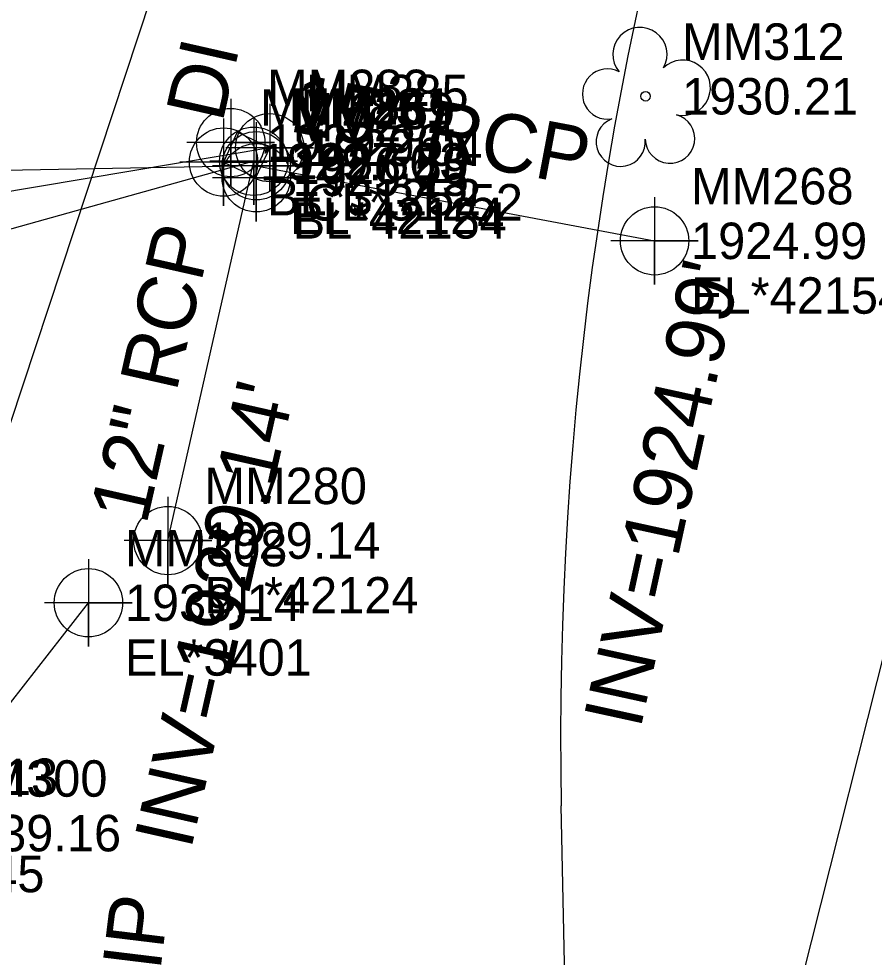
# Model space of a CAD drawing. Extents: x 1004514 to 1005247, y 553695 to 554706.
# Drawn here: x 1004934 to 1004992.7, y 554126.5 to 554190.9 of the extents above; entities that cross this region are included whole.
import ezdxf

# ---------------------------------------------------------------- set-up
doc = ezdxf.new("R2010")
doc.units = 0
for name, color, linetype in [('Exist Building', 7, 'Continuous'), ('Exist Building Cogo Elevation', 7, 'Continuous'), ('Exist Building Cogo Number', 7, 'Continuous'), ('Exist Building Cogo Point CELL', 7, 'Continuous'), ('Exist Property Iron Pin Text', 7, 'Continuous'), ('Exist Right of Way Line', 7, 'Continuous'), ('Exist Structure Minor Drop Inlet', 7, 'Continuous'), ('Exist Structure Minor Drop Inlet Cogo Comment', 7, 'Continuous'), ('Exist Structure Minor Drop Inlet Cogo Elevation', 7, 'Continuous'), ('Exist Structure Minor Drop Inlet Cogo Number', 7, 'Continuous'), ('Exist Structure Minor Drop Inlet Cogo Point CELL', 7, 'Continuous'), ('Exist Structure Minor Drop Inlet Leader', 7, 'Continuous'), ('Exist Structure Minor Drop Inlet Text', 7, 'Continuous'), ('Exist Structure Minor Pipes RCP 12 Inch', 7, 'Continuous'), ('Exist Structure Minor Pipes RCP 12 Inch Cogo Comment', 7, 'Continuous'), ('Exist Structure Minor Pipes RCP 12 Inch Cogo Number', 7, 'Continuous'), ('Exist Structure Minor Pipes RCP 12 Inch Cogo Point CELL', 7, 'Continuous'), ('Exist Structure Minor Pipes RCP 12 Inch Invert', 7, 'Continuous'), ('Exist Structure Minor Pipes RCP 12 Inch Leader', 7, 'Continuous'), ('Exist Structure Minor Pipes RCP 12 Inch Text', 7, 'Continuous'), ('Exist Structure Minor Pipes RCP 15 Inch', 7, 'Continuous'), ('Exist Structure Minor Pipes RCP 15 Inch Cogo Comment', 7, 'Continuous'), ('Exist Structure Minor Pipes RCP 15 Inch Cogo Elevation', 7, 'Continuous'), ('Exist Structure Minor Pipes RCP 15 Inch Cogo Number', 7, 'Continuous'), ('Exist Structure Minor Pipes RCP 15 Inch Cogo Point CELL', 7, 'Continuous'), ('Exist Structure Minor Pipes RCP 15 Inch Invert', 7, 'Continuous'), ('Exist Structure Minor Pipes RCP 15 Inch Leader', 7, 'Continuous'), ('Exist Structure Minor Pipes RCP 15 Inch Text', 7, 'Continuous'), ('Exist Vegetation Tree CELL', 7, 'Continuous'), ('Exist Vegetation Tree Cogo Elevation', 7, 'Continuous'), ('Exist Vegetation Tree Cogo Number', 7, 'Continuous'), ('Exist Vegetation Woods Line Cogo Comment', 7, 'Continuous'), ('Old_Level_3', 7, 'Continuous'), ('Scratch_Level_3', 7, 'Continuous')]:
    doc.layers.add(name, color=color, linetype=linetype)

msp = doc.modelspace()

# ---------------------------------------------------------------- linework, layer by layer
at = {"layer": 'Exist Building'}
msp.add_line((1004926.468, 554135.051), (1004938.808, 554150.855), dxfattribs=at)
at = {"layer": 'Exist Building Cogo Point CELL'}
msp.add_lwpolyline([(1004938.808, 554153.855), (1004938.808, 554147.855), (1004938.808, 554150.855), (1004941.808, 554150.855), (1004935.808, 554150.855)], dxfattribs=at)
msp.add_circle((1004938.808, 554150.855), 2.344, dxfattribs=at)
at = {"layer": 'Exist Right of Way Line'}
msp.add_line((1004974.633, 553969.453), (1004971.246, 554136.929), dxfattribs=at)
msp.add_arc((1005209.198, 554141.741), 238, 143.26447, 181.15854, dxfattribs=at)
at = {"layer": 'Exist Structure Minor Drop Inlet'}
msp.add_lwpolyline([(1004948.079, 554181.091), (1004950.3, 554180.028), (1004951.243, 554182.08), (1004949.022, 554183.143)], close=True, dxfattribs=at)
at = {"layer": 'Exist Structure Minor Drop Inlet Cogo Point CELL'}
for points in [[(1004948.569, 554185.432), (1004948.569, 554179.432), (1004948.569, 554182.432), (1004951.569, 554182.432), (1004945.569, 554182.432)], [(1004951.243, 554185.08), (1004951.243, 554179.08), (1004951.243, 554182.08), (1004954.243, 554182.08), (1004948.243, 554182.08)], [(1004948.079, 554184.091), (1004948.079, 554178.091), (1004948.079, 554181.091), (1004951.079, 554181.091), (1004945.079, 554181.091)], [(1004950.322, 554183.017), (1004950.322, 554177.017), (1004950.322, 554180.017), (1004953.322, 554180.017), (1004947.322, 554180.017)]]:
    msp.add_lwpolyline(points, dxfattribs=at)
for centre in [(1004948.569, 554182.432), (1004951.243, 554182.08), (1004948.079, 554181.091), (1004950.322, 554180.017)]:
    msp.add_circle(centre, 2.344, dxfattribs=at)
at = {"layer": 'Exist Structure Minor Drop Inlet Leader'}
msp.add_lwpolyline([(1004951.243, 554182.08), (1004919.348, 554176.707), (1004921.33, 554184.761)], dxfattribs=at)
at = {"layer": 'Exist Structure Minor Pipes RCP 12 Inch'}
msp.add_line((1004944.265, 554155.124), (1004950.148, 554181.151), dxfattribs=at)
at = {"layer": 'Exist Structure Minor Pipes RCP 12 Inch Cogo Point CELL'}
for points in [[(1004950.148, 554184.151), (1004950.148, 554178.151), (1004950.148, 554181.151), (1004953.148, 554181.151), (1004947.148, 554181.151)], [(1004944.265, 554158.124), (1004944.265, 554152.124), (1004944.265, 554155.124), (1004947.265, 554155.124), (1004941.265, 554155.124)]]:
    msp.add_lwpolyline(points, dxfattribs=at)
for centre in [(1004950.148, 554181.151), (1004944.265, 554155.124)]:
    msp.add_circle(centre, 2.344, dxfattribs=at)
at = {"layer": 'Exist Structure Minor Pipes RCP 12 Inch Leader'}
msp.add_lwpolyline([(1004950.148, 554181.151), (1004919.229, 554172.517), (1004912.103, 554175.631)], dxfattribs=at)
at = {"layer": 'Exist Structure Minor Pipes RCP 15 Inch'}
msp.add_line((1004950.32, 554180.839), (1004977.646, 554175.688), dxfattribs=at)
at = {"layer": 'Exist Structure Minor Pipes RCP 15 Inch Cogo Point CELL'}
for points in [[(1004950.32, 554183.839), (1004950.32, 554177.839), (1004950.32, 554180.839), (1004953.32, 554180.839), (1004947.32, 554180.839)], [(1004977.646, 554178.688), (1004977.646, 554172.688), (1004977.646, 554175.688), (1004980.646, 554175.688), (1004974.646, 554175.688)]]:
    msp.add_lwpolyline(points, dxfattribs=at)
for centre in [(1004950.32, 554180.839), (1004977.646, 554175.688)]:
    msp.add_circle(centre, 2.344, dxfattribs=at)
at = {"layer": 'Exist Structure Minor Pipes RCP 15 Inch Leader'}
msp.add_lwpolyline([(1004950.32, 554180.839), (1004925.653, 554180.369), (1004927.196, 554186.167)], dxfattribs=at)
at = {"layer": 'Exist Vegetation Tree CELL'}
msp.add_line((1004977.028, 554185.605), (1004977.028, 554185.605), dxfattribs=at)
msp.add_circle((1004977.028, 554185.605), 0.326, dxfattribs=at)
for centre, radius, start, end in [((1004976.643, 554188.478), 1.856, 330.16508, 219.71335), ((1004979.577, 554186.193), 1.899, 257.1011, 134.19993), ((1004974.422, 554185.758), 1.727, 62.66361, 279.3457), ((1004978.701, 554182.705), 1.698, 181.28216, 74.55999), ((1004975.324, 554182.484), 1.689, 111.56708, 6.23104)]:
    msp.add_arc(centre, radius, start, end, dxfattribs=at)
at = {"layer": 'Old_Level_3'}
msp.add_line((1004908.043, 554086.33), (1004974.392, 554286.954), dxfattribs=at)
at = {"layer": 'Scratch_Level_3'}
msp.add_line((1004952.617, 553985.711), (1005030.054, 554292.752), dxfattribs=at)

# ---------------------------------------------------------------- texts
at = {"layer": 'Exist Building Cogo Elevation'}
for s, p in [('1939.14', (1004941.308, 554149.605)), ('EL*3401', (1004941.308, 554145.855)), ('BL*34013', (1004922.043, 554137.67)), ('1939.16', (1004928.968, 554133.801))]:
    msp.add_text(s, height=2.5, dxfattribs=at).set_placement(p)
at = {"layer": 'Exist Building Cogo Number'}
for s, p in [('MM308', (1004941.308, 554153.355)), ('MM300', (1004928.968, 554137.551))]:
    msp.add_text(s, height=2.5, dxfattribs=at).set_placement(p)
at = {"layer": 'Exist Property Iron Pin Text'}
msp.add_text('EIP', height=4, rotation=83.04421, dxfattribs=at).set_placement((1004943.308, 554121.998))
at = {"layer": 'Exist Structure Minor Drop Inlet Cogo Comment'}
for s, p in [('BL*31252', (1004951.069, 554177.432)), ('CL*31252', (1004953.743, 554177.08))]:
    msp.add_text(s, height=2.5, dxfattribs=at).set_placement(p)
at = {"layer": 'Exist Structure Minor Drop Inlet Cogo Elevation'}
for s, p in [('1929.26', (1004951.069, 554181.182)), ('1929.04', (1004953.743, 554180.83)), ('1929.66', (1004950.579, 554179.841)), ('1929.25', (1004952.822, 554178.767))]:
    msp.add_text(s, height=2.5, dxfattribs=at).set_placement(p)
at = {"layer": 'Exist Structure Minor Drop Inlet Cogo Number'}
for s, p in [('MM282', (1004951.069, 554184.932)), ('MM285', (1004953.743, 554184.58)), ('MM283', (1004950.579, 554183.591)), ('MM284', (1004952.822, 554182.517))]:
    msp.add_text(s, height=2.5, dxfattribs=at).set_placement(p)
at = {"layer": 'Exist Structure Minor Drop Inlet Text'}
msp.add_text('DI', height=4, rotation=77.26235, dxfattribs=at).set_placement((1004947.999, 554183.724))
at = {"layer": 'Exist Structure Minor Pipes RCP 12 Inch Cogo Comment'}
for s, p in [('1927.23', (1004952.648, 554179.901)), ('EL*42124', (1004952.648, 554176.151)), ('1929.14', (1004946.765, 554153.874)), ('BL*42124', (1004946.765, 554150.124))]:
    msp.add_text(s, height=2.5, dxfattribs=at).set_placement(p)
at = {"layer": 'Exist Structure Minor Pipes RCP 12 Inch Cogo Number'}
for s, p in [('MM281', (1004952.648, 554183.651)), ('MM280', (1004946.765, 554157.624))]:
    msp.add_text(s, height=2.5, dxfattribs=at).set_placement(p)
at = {"layer": 'Exist Structure Minor Pipes RCP 12 Inch Invert'}
msp.add_text("INV=1929.14'", height=4, rotation=77.26549, dxfattribs=at).set_placement((1004945.84, 554133.838))
at = {"layer": 'Exist Structure Minor Pipes RCP 12 Inch Text'}
msp.add_text('12" RCP', height=4, rotation=77.26235, dxfattribs=at).set_placement((1004942.78, 554156.133))
at = {"layer": 'Exist Structure Minor Pipes RCP 15 Inch Cogo Comment'}
for s, p in [('BL*42154', (1004952.82, 554175.839)), ('EL*42154', (1004980.146, 554170.688))]:
    msp.add_text(s, height=2.5, dxfattribs=at).set_placement(p)
at = {"layer": 'Exist Structure Minor Pipes RCP 15 Inch Cogo Elevation'}
for s, p in [('1926.59', (1004952.82, 554179.589)), ('1924.99', (1004980.146, 554174.438))]:
    msp.add_text(s, height=2.5, dxfattribs=at).set_placement(p)
at = {"layer": 'Exist Structure Minor Pipes RCP 15 Inch Cogo Number'}
for s, p in [('MM259', (1004952.82, 554183.339)), ('MM268', (1004980.146, 554178.188))]:
    msp.add_text(s, height=2.5, dxfattribs=at).set_placement(p)
at = {"layer": 'Exist Structure Minor Pipes RCP 15 Inch Invert'}
for s, rotation, p in [("INV=1926.59'", 75.09829, (1004929.643, 554187.585)), ("INV=1924.99'", 77.69047, (1004976.671, 554142.114))]:
    msp.add_text(s, height=4, rotation=rotation, dxfattribs=at).set_placement(p)
at = {"layer": 'Exist Structure Minor Pipes RCP 15 Inch Text'}
msp.add_text('15" RCP', height=4, rotation=349.32564, dxfattribs=at).set_placement((1004952.504, 554183.226))
at = {"layer": 'Exist Vegetation Tree Cogo Elevation'}
msp.add_text('1930.21', height=2.5, dxfattribs=at).set_placement((1004979.528, 554184.355))
at = {"layer": 'Exist Vegetation Tree Cogo Number'}
msp.add_text('MM312', height=2.5, dxfattribs=at).set_placement((1004979.528, 554188.105))
at = {"layer": 'Exist Vegetation Woods Line Cogo Comment'}
msp.add_text('BL*36045', height=2.5, dxfattribs=at).set_placement((1004921.105, 554130.996))

doc.saveas('drawing.dxf')
